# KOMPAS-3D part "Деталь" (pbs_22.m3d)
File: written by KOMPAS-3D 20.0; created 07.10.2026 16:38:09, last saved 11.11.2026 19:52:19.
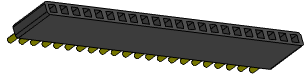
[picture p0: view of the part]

Document properties: Полное имя файла: D:\myProjects\Progect_esp32\box_compas\разъемы\pbs_22.m3d

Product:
- Part/product: Деталь
    Масса: 0.00671403

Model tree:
1. Эскиз:1
2. Элемент выдавливания:1
     Расстояние 1 = 8.5
3. Эскиз:2  (with: Элемент выдавливания:1)
4. Элемент выдавливания:2
     Расстояние 1 = 3
5. Массив по сетке:2  (with: Элемент выдавливания:2, Эскиз:2)  (22 pattern instances)
     Шаг 1 = 2.54; Угол раствора = 90
6. Эскиз:3  (with: Элемент выдавливания:1)
7. Элемент выдавливания:3
     Расстояние 2 = 8
8. Массив по сетке:3  (with: Элемент выдавливания:3, Эскиз:3)  (22 pattern instances)
     Шаг 1 = 2.54; Угол раствора = 90; Геометрический массив = 128
9. Скругление:1  (with: Элемент выдавливания:1)
     Радиус = 0.5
